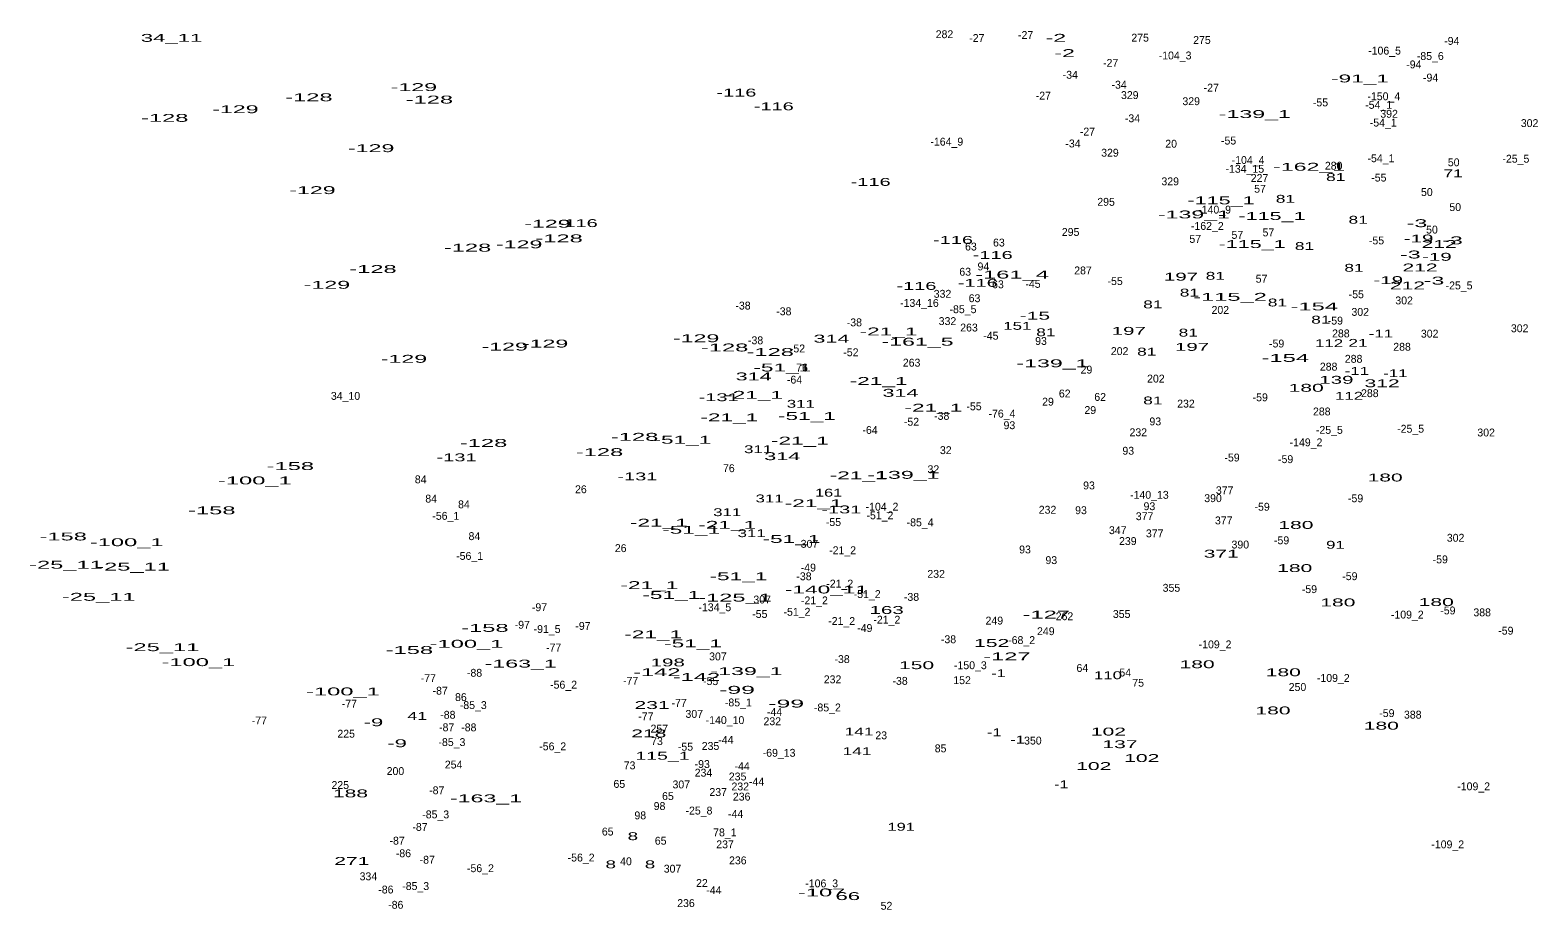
# Model space of a CAD drawing. Extents: x -662499 to -659675, y -1001682 to -998165.
# Drawn here: x -661764 to -660998, y -1000395 to -999948 of the extents above; entities that cross this region are included whole.
import ezdxf
from ezdxf.enums import TextEntityAlignment as Align

# ---------------------------------------------------------------- set-up
doc = ezdxf.new("R2010")
doc.units = 0
doc.header["$LTSCALE"] = 1.6
doc.layers.add('24', color=7, linetype='Continuous')

msp = doc.modelspace()

# ---------------------------------------------------------------- texts
at = {"layer": '24'}
for s, width, p in [('34_11', 2.1, (-661692.001, -999953.42)), ('-2', 2.2, (-661242.514, -999953.4)), ('-2', 2.2, (-661238.054, -999961.16)), ('-129', 2.2, (-661568.805, -999978.44)), ('-91_1', 2.15, (-661087.923, -999974.05)), ('-128', 2.25, (-661622.181, -999983.6)), ('-128', 2.25, (-661560.921, -999984.77)), ('-116', 1.9, (-661404.881, -999981.23)), ('-128', 2.25, (-661695.471, -999994.08)), ('-129', 2.2, (-661659.535, -999989.68)), ('-116', 1.9, (-661385.891, -999988.21)), ('-139_1', 2.2, (-661141.393, -999992.13)), ('-129', 2.2, (-661590.515, -1000009.47)), ('-162_1', 2.2, (-661113.763, -1000018.92)), ('81', 1.65, (-661100.267, -1000024.16)), ('71', 1.65, (-661040.593, -1000022.28)), ('-129', 2.2, (-661620.375, -1000030.8)), ('-116', 1.9, (-661336.641, -1000026.61)), ('-115_1', 2.05, (-661158.544, -1000035.99)), ('81', 1.65, (-661125.817, -1000035.2)), ('-129', 2.2, (-661500.945, -1000047.87)), ('-116', 1.9, (-661485.531, -1000047.56)), ('-139_1', 2.2, (-661172.333, -1000043.15)), ('-115_1', 2.05, (-661132.654, -1000043.94)), ('81', 1.65, (-661088.837, -1000045.85)), ('-3', 2.2, (-661058.934, -1000047.59)), ('-128', 2.25, (-661495.011, -1000055.31)), ('-116', 1.9, (-661294.771, -1000056.09)), ('-19', 1.95, (-661058.145, -1000055.38)), ('-3', 2.2, (-661040.904, -1000056.32)), ('-128', 2.25, (-661541.541, -1000060.02)), ('-129', 2.2, (-661515.295, -1000058.34)), ('-116', 1.9, (-661274.611, -1000063.76)), ('-115_1', 2.05, (-661142.734, -1000058.2)), ('81', 1.65, (-661116.137, -1000059.22)), ('-3', 2.2, (-661062.314, -1000063.5)), ('212', 2, (-661047.707, -1000058.19)), ('-128', 2.25, (-661589.611, -1000070.88)), ('81', 1.65, (-661090.967, -1000070.26)), ('212', 2, (-661057.407, -1000070.11)), ('-19', 1.95, (-661048.845, -1000064.68)), ('-129', 2.2, (-661613.005, -1000078.9)), ('-116', 1.9, (-661313.381, -1000079.47)), ('-116', 1.9, (-661282.171, -1000077.91)), ('-161_4', 2.25, (-661264.788, -1000073.7)), ('197', 1.95, (-661178.897, -1000074.77)), ('81', 1.65, (-661161.447, -1000074.33)), ('-19', 1.95, (-661073.555, -1000076.52)), ('212', 2, (-661063.797, -1000079.23)), ('-3', 2.2, (-661050.304, -1000076.78)), ('81', 1.65, (-661174.617, -1000082.85)), ('-115_2', 2.25, (-661153.987, -1000085.02)), ('-15', 2, (-661253.171, -1000094.61)), ('81', 1.65, (-661193.207, -1000088.86)), ('81', 1.65, (-661129.887, -1000087.89)), ('-154', 2.25, (-661111.156, -1000089.9)), ('-21_1', 2.15, (-661327.577, -1000102.61)), ('151', 1.6, (-661262.104, -1000099.76)), ('197', 1.95, (-661205.457, -1000102.31)), ('81', 1.65, (-661107.817, -1000096.61)), ('-129', 2.2, (-661522.665, -1000110.31)), ('-129', 2.2, (-661502.115, -1000108.76)), ('-129', 2.2, (-661425.345, -1000106.05)), ('314', 2.05, (-661356.573, -1000106.26)), ('-161_5', 2.2, (-661312.823, -1000107.81)), ('81', 1.65, (-661247.577, -1000103)), ('197', 1.95, (-661173.277, -1000110.45)), ('81', 1.65, (-661175.197, -1000103.19)), ('112', 1.6, (-661103.624, -1000108.56)), ('21', 1.65, (-661088.927, -1000108.41)), ('-11', 1.6, (-661077.297, -1000103.65)), ('-129', 2.2, (-661573.845, -1000116.52)), ('-128', 2.25, (-661410.871, -1000110.75)), ('-128', 2.25, (-661387.681, -1000113.07)), ('81', 1.65, (-661196.307, -1000112.88)), ('-154', 2.25, (-661125.896, -1000116.07)), ('314', 2.05, (-661396.123, -1000125.46)), ('-51_1', 2.15, (-661381.547, -1000120.95)), ('-139_1', 2.2, (-661244.253, -1000118.79)), ('-11', 1.6, (-661089.517, -1000122.66)), ('-11', 1.6, (-661069.937, -1000123.82)), ('-21_1', 2.15, (-661332.617, -1000127.79)), ('180', 2, (-661115.274, -1000131.24)), ('139', 1.95, (-661099.923, -1000127.18)), ('312', 2, (-661076.697, -1000128.94)), ('-131', 1.9, (-661413.917, -1000136.03)), ('-21_1', 2.15, (-661395.897, -1000134.82)), ('311', 1.6, (-661372.134, -1000139.37)), ('314', 2.05, (-661321.483, -1000133.8)), ('81', 1.65, (-661193.207, -1000137.67)), ('112', 1.6, (-661093.464, -1000135.29)), ('-21_1', 2.15, (-661408.497, -1000146.26)), ('-51_1', 2.15, (-661369.047, -1000145.58)), ('-21_1', 2.15, (-661304.757, -1000141.36)), ('-128', 2.25, (-661456.621, -1000156.16)), ('-128', 2.25, (-661533.391, -1000159.26)), ('-128', 2.25, (-661474.461, -1000163.92)), ('-51_1', 2.15, (-661432.347, -1000157.64)), ('311', 1.6, (-661393.844, -1000162.45)), ('-21_1', 2.15, (-661372.627, -1000158.09)), ('-158', 2.25, (-661631.601, -1000171.02)), ('-131', 1.9, (-661547.107, -1000166.58)), ('314', 2.05, (-661381.583, -1000165.99)), ('-100_1', 2.25, (-661649.65, -1000178.31)), ('-131', 1.9, (-661455.217, -1000176.27)), ('-21_1', 2.15, (-661342.777, -1000175.74)), ('-139_1', 2.2, (-661319.983, -1000175.47)), ('180', 2, (-661075.144, -1000176.82)), ('161', 1.55, (-661358.009, -1000184.54)), ('-158', 2.25, (-661671.531, -1000193.51)), ('311', 1.6, (-661409.544, -1000194.45)), ('311', 1.6, (-661388.024, -1000187.47)), ('-21_1', 2.15, (-661365.647, -1000189.89)), ('-131', 1.9, (-661351.547, -1000193.05)), ('-21_1', 2.15, (-661444.317, -1000199.79)), ('-21_1', 2.15, (-661409.577, -1000200.87)), ('180', 2, (-661120.504, -1000200.93)), ('-158', 2.25, (-661747.061, -1000206.79)), ('-100_1', 2.25, (-661714.79, -1000209.71)), ('-51_1', 2.15, (-661427.887, -1000203.39)), ('311', 1.6, (-661397.144, -1000205.12)), ('-51_1', 2.15, (-661376.897, -1000208.05)), ('371', 2, (-661158.443, -1000215.53)), ('91', 1.6, (-661100.403, -1000211.01)), ('-25_11', 2.25, (-661745.657, -1000221.16)), ('-25_11', 2.25, (-661711.537, -1000222.13)), ('180', 2, (-661121.084, -1000222.85)), ('-21_1', 2.15, (-661449.127, -1000231.51)), ('-51_1', 2.15, (-661403.847, -1000227)), ('-25_11', 2.25, (-661728.987, -1000237.45)), ('-51_1', 2.15, (-661437.967, -1000236.5)), ('-125_1', 2.25, (-661405.587, -1000237.86)), ('-140_11', 2.15, (-661359.126, -1000233.73)), ('180', 2, (-661099.184, -1000240.3)), ('180', 2, (-661049.164, -1000240.11)), ('163', 1.95, (-661328.513, -1000244.15)), ('-127', 2.25, (-661247.355, -1000246.49)), ('-158', 2.25, (-661532.721, -1000253.25)), ('-25_11', 2.25, (-661696.607, -1000263.05)), ('-100_1', 2.25, (-661542.06, -1000261.32)), ('-21_1', 2.15, (-661447.187, -1000256.53)), ('-51_1', 2.15, (-661426.917, -1000261.13)), ('152', 2, (-661275.127, -1000260.92)), ('-100_1', 2.25, (-661678.35, -1000270.65)), ('-158', 2.25, (-661571.111, -1000264.5)), ('-163_1', 2.2, (-661514.503, -1000271.4)), ('198', 1.95, (-661439.783, -1000270.8)), ('-127', 2.25, (-661267.415, -1000267.73)), ('-142', 2.25, (-661445.326, -1000275.75)), ('-142', 2.25, (-661425.166, -1000278.18)), ('-139_1', 2.2, (-661399.743, -1000275.21)), ('150', 2, (-661313.304, -1000272.2)), ('-1', 1.55, (-661271.691, -1000276.25)), ('110', 1.6, (-661216.02, -1000277.3)), ('180', 2, (-661170.714, -1000271.72)), ('180', 2, (-661126.904, -1000275.79)), ('-100_1', 2.25, (-661604.87, -1000285.54)), ('-99', 2.35, (-661404.573, -1000284.72)), ('231', 2, (-661447.757, -1000292.44)), ('-99', 2.35, (-661379.563, -1000291.7)), ('-9', 2.1, (-661589.379, -1000301.2)), ('41', 1.7, (-661567.083, -1000297.97)), ('180', 2, (-661132.134, -1000295.19)), ('218', 2, (-661449.397, -1000306.86)), ('141', 1.65, (-661342.519, -1000305.92)), ('-1', 1.55, (-661273.821, -1000306.32)), ('102', 2, (-661215.784, -1000305.93)), ('180', 2, (-661077.084, -1000302.94)), ('-9', 2.1, (-661577.359, -1000311.87)), ('141', 1.65, (-661343.579, -1000315.91)), ('-1', 1.55, (-661262.001, -1000310)), ('137', 2, (-661209.913, -1000312.35)), ('115_1', 1.85, (-661442.461, -1000318.22)), ('102', 2, (-661223.234, -1000323.46)), ('102', 2, (-661198.834, -1000319.39)), ('-1', 1.55, (-661239.701, -1000332.69)), ('188', 2, (-661601.037, -1000337.35)), ('-163_1', 2.2, (-661532.143, -1000339.86)), ('191', 1.55, (-661321.129, -1000354.3)), ('8', 1.8, (-661457.511, -1000359.08)), ('271', 2, (-661600.343, -1000371.67)), ('8', 1.8, (-661468.741, -1000373.41)), ('8', 1.8, (-661448.791, -1000373.41)), ('-107', 2.25, (-661361.551, -1000387.68)), ('66', 2.1, (-661348.251, -1000389.55))]:
    msp.add_text(s, height=4, dxfattribs=dict(at, width=width)).set_placement(p, align=Align.CENTER)
for s, p in [('282', (-661299.117, -999951.56)), ('-27', (-661282.681, -999953.52)), ('-27', (-661257.871, -999951.97)), ('275', (-661199.663, -999953.32)), ('275', (-661168.263, -999954.49)), ('-94', (-661041.265, -999954.98)), ('-104_3', (-661181.904, -999962.36)), ('-106_5', (-661075.436, -999959.91)), ('-85_6', (-661052.188, -999962.65)), ('-34', (-661235.169, -999972.18)), ('-27', (-661214.641, -999966.13)), ('-94', (-661060.555, -999966.9)), ('-34', (-661210.349, -999977.22)), ('-27', (-661163.511, -999978.73)), ('-94', (-661052.025, -999973.59)), ('-27', (-661248.851, -999982.76)), ('329', (-661204.933, -999982.5)), ('329', (-661173.713, -999985.6)), ('-55', (-661107.985, -999986.22)), ('-54_1', (-661078.42, -999987.45)), ('-150_4', (-661075.804, -999983.11)), ('-34', (-661203.569, -999994.29)), ('392', (-661073.123, -999992)), ('-27', (-661226.461, -1000001.04)), ('-54_1', (-661076.1, -999996.46)), ('302', (-661001.711, -999996.74)), ('-164_9', (-661297.941, -1000006.16)), ('-34', (-661233.809, -1000007.09)), ('20', (-661183.911, -1000007.21)), ('-55', (-661154.705, -1000005.61)), ('329', (-661215.013, -1000011.78)), ('-104_4', (-661144.809, -1000015.51)), ('280', (-661101.311, -1000018.39)), ('-54_1', (-661077.26, -1000014.6)), ('50', (-661040.291, -1000016.66)), ('-25_5', (-661008.682, -1000014.83)), ('329', (-661184.383, -1000026.33)), ('-134_15', (-661146.463, -1000019.95)), ('227', (-661138.983, -1000024.61)), ('-55', (-661078.325, -1000024.42)), ('57', (-661138.733, -1000030.1)), ('50', (-661053.941, -1000031.77)), ('295', (-661216.973, -1000036.74)), ('-140_9', (-661161.83, -1000040.71)), ('50', (-661039.521, -1000039.42)), ('-162_2', (-661165.522, -1000048.99)), ('295', (-661235.003, -1000052.06)), ('57', (-661171.653, -1000055.58)), ('57', (-661150.253, -1000053.54)), ('57', (-661134.473, -1000052.28)), ('-55', (-661079.525, -1000056.36)), ('50', (-661051.331, -1000050.85)), ('63', (-661285.683, -1000059.47)), ('63', (-661271.453, -1000057.44)), ('63', (-661288.593, -1000072.26)), ('94', (-661279.337, -1000069.56)), ('287', (-661228.713, -1000071.6)), ('63', (-661271.943, -1000078.66)), ('-45', (-661254.119, -1000078.42)), ('-55', (-661212.365, -1000077.02)), ('57', (-661137.953, -1000075.82)), ('-25_5', (-661037.562, -1000079.22)), ('332', (-661300.117, -1000083.48)), ('63', (-661283.843, -1000085.72)), ('-55', (-661089.795, -1000083.71)), ('302', (-661065.491, -1000086.84)), ('-38', (-661401.525, -1000089.47)), ('-38', (-661380.775, -1000092.37)), ('-134_16', (-661311.859, -1000088.1)), ('-85_5', (-661289.722, -1000091.31)), ('202', (-661158.911, -1000091.66)), ('302', (-661087.791, -1000092.66)), ('-38', (-661344.915, -1000098)), ('332', (-661297.597, -1000097.35)), ('263', (-661286.643, -1000100.62)), ('-59', (-661100.43, -1000097.1)), ('302', (-661006.751, -1000101)), ('-38', (-661395.125, -1000107.11)), ('-45', (-661275.539, -1000104.79)), ('93', (-661250.053, -1000107.44)), ('-59', (-661130.29, -1000108.74)), ('288', (-661097.647, -1000103.61)), ('288', (-661066.537, -1000110.4)), ('302', (-661052.501, -1000103.72)), ('-52', (-661373.835, -1000111.25)), ('-52', (-661346.685, -1000113.19)), ('202', (-661210.091, -1000112.6)), ('288', (-661091.157, -1000116.51)), ('76', (-661371.548, -1000120.96)), ('263', (-661315.823, -1000118.47)), ('29', (-661226.953, -1000122.02)), ('288', (-661103.857, -1000120.49)), ('-64', (-661375.345, -1000127.09)), ('202', (-661191.671, -1000126.57)), ('34_10', (-661603.547, -1000135.35)), ('-55', (-661284.095, -1000140.64)), ('29', (-661246.513, -1000138.29)), ('62', (-661237.993, -1000134.14)), ('62', (-661219.983, -1000135.88)), ('232', (-661176.377, -1000139.29)), ('-59', (-661138.62, -1000136.08)), ('288', (-661082.917, -1000133.97)), ('-52', (-661315.875, -1000148.49)), ('-38', (-661300.515, -1000145.51)), ('-76_4', (-661269.898, -1000144.36)), ('29', (-661225.023, -1000142.56)), ('93', (-661191.963, -1000148.31)), ('288', (-661107.347, -1000143.27)), ('-64', (-661336.955, -1000152.69)), ('93', (-661266.123, -1000150.25)), ('232', (-661200.607, -1000153.84)), ('-25_5', (-661103.482, -1000152.63)), ('-25_5', (-661062.192, -1000152.05)), ('302', (-661023.811, -1000153.95)), ('32', (-661298.457, -1000162.93)), ('93', (-661205.713, -1000163.23)), ('-149_2', (-661115.356, -1000158.96)), ('-59', (-661152.97, -1000166.67)), ('-59', (-661125.73, -1000167.5)), ('84', (-661565.361, -1000177.77)), ('76', (-661408.728, -1000172.1)), ('32', (-661304.747, -1000172.62)), ('26', (-661483.933, -1000182.8)), ('93', (-661225.653, -1000180.85)), ('-140_13', (-661194.957, -1000185.63)), ('377', (-661156.709, -1000183.31)), ('84', (-661560.031, -1000187.55)), ('84', (-661543.381, -1000190.46)), ('-104_2', (-661330.874, -1000191.65)), ('232', (-661246.747, -1000193.21)), ('93', (-661229.723, -1000193.44)), ('93', (-661194.953, -1000191.42)), ('390', (-661162.617, -1000187.33)), ('-59', (-661137.65, -1000191.69)), ('-59', (-661090.16, -1000187.4)), ('-56_1', (-661552.602, -1000196.31)), ('-55', (-661355.555, -1000199.46)), ('-51_2', (-661331.926, -1000196.04)), ('-85_4', (-661311.507, -1000199.62)), ('377', (-661197.419, -1000196.49)), ('377', (-661157.189, -1000198.63)), ('84', (-661538.061, -1000206.63)), ('347', (-661211.047, -1000203.59)), ('239', (-661205.933, -1000209.12)), ('377', (-661192.279, -1000205.21)), ('-59', (-661127.77, -1000208.74)), ('302', (-661039.321, -1000207.45)), ('-56_1', (-661540.482, -1000216.67)), ('26', (-661463.693, -1000212.72)), ('307', (-661367.747, -1000210.52)), ('-21_2', (-661350.906, -1000213.78)), ('93', (-661258.183, -1000213.39)), ('390', (-661148.757, -1000210.89)), ('-49', (-661368.315, -1000222.58)), ('93', (-661244.823, -1000218.82)), ('-59', (-661047.12, -1000218.43)), ('-38', (-661370.545, -1000227.02)), ('-21_2', (-661352.356, -1000230.75)), ('232', (-661303.357, -1000225.79)), ('355', (-661183.757, -1000232.88)), ('-59', (-661093.06, -1000226.97)), ('307', (-661391.797, -1000238.83)), ('-21_2', (-661365.246, -1000239.28)), ('-51_2', (-661338.416, -1000236.07)), ('-38', (-661315.875, -1000237.49)), ('-59', (-661113.61, -1000233.56)), ('-97', (-661504.975, -1000242.74)), ('-134_5', (-661415.85, -1000242.76)), ('-55', (-661392.975, -1000246.17)), ('-51_2', (-661374.096, -1000245.08)), ('262', (-661238.133, -1000247.33)), ('355', (-661209.057, -1000246.17)), ('-109_2', (-661063.876, -1000246.49)), ('-59', (-661043.24, -1000244.38)), ('388', (-661025.817, -1000245.35)), ('-97', (-661513.705, -1000251.66)), ('-91_5', (-661501.102, -1000253.82)), ('-97', (-661482.875, -1000252.24)), ('-21_2', (-661351.386, -1000249.76)), ('-49', (-661339.625, -1000253.32)), ('-21_2', (-661328.416, -1000249.08)), ('249', (-661273.787, -1000249.54)), ('249', (-661247.617, -1000254.92)), ('-59', (-661013.77, -1000254.66)), ('-77', (-661497.775, -1000263.24)), ('-38', (-661297.065, -1000259.02)), ('-68_2', (-661259.908, -1000259.45)), ('-109_2', (-661161.586, -1000261.62)), ('307', (-661414.277, -1000267.73)), ('-38', (-661351.155, -1000269.11)), ('-77', (-661561.465, -1000278.76)), ('-88', (-661537.975, -1000276.07)), ('-150_3', (-661285.96, -1000272.22)), ('64', (-661229.047, -1000273.62)), ('54', (-661207.231, -1000275.91)), ('-109_2', (-661101.486, -1000278.68)), ('-87', (-661555.441, -1000285.16)), ('-56_2', (-661492.728, -1000282.1)), ('-77', (-661458.615, -1000280.12)), ('-55', (-661417.975, -1000280.3)), ('232', (-661356.007, -1000279.39)), ('-38', (-661321.685, -1000280.16)), ('152', (-661290.169, -1000279.82)), ('75', (-661200.683, -1000281.14)), ('250', (-661119.691, -1000283.29)), ('-77', (-661601.595, -1000291.75)), ('86', (-661544.913, -1000288.43)), ('-85_3', (-661538.632, -1000292.48)), ('-77', (-661433.995, -1000291.36)), ('-85_1', (-661403.896, -1000291.13)), ('-85_2', (-661358.642, -1000293.68)), ('-77', (-661647.345, -1000300.29)), ('-88', (-661551.545, -1000297.4)), ('-77', (-661450.865, -1000298.15)), ('307', (-661426.297, -1000296.95)), ('-140_10', (-661410.681, -1000300.11)), ('232', (-661386.647, -1000300.68)), ('-44', (-661385.503, -1000295.97)), ('-59', (-661074.26, -1000296.55)), ('388', (-661061.097, -1000297.33)), ('225', (-661603.237, -1000307.02)), ('-87', (-661552.141, -1000303.77)), ('-88', (-661540.885, -1000303.8)), ('257', (-661444.063, -1000304.42)), ('23', (-661331.277, -1000307.84)), ('-85_3', (-661549.482, -1000311.29)), ('-56_2', (-661498.248, -1000313.44)), ('73', (-661445.243, -1000310.78)), ('-55', (-661430.775, -1000313.63)), ('235', (-661418.037, -1000313.25)), ('-44', (-661410.223, -1000310.13)), ('-69_13', (-661383.187, -1000316.72)), ('85', (-661301.097, -1000314.46)), ('350', (-661254.191, -1000310.51)), ('254', (-661548.621, -1000322.69)), ('73', (-661459.173, -1000323.09)), ('-93', (-661422.24, -1000322.43)), ('-44', (-661401.983, -1000323.49)), ('200', (-661578.185, -1000326)), ('65', (-661464.383, -1000332.53)), ('307', (-661432.897, -1000332.79)), ('234', (-661421.621, -1000326.82)), ('235', (-661404.267, -1000328.76)), ('-44', (-661394.613, -1000331.37)), ('225', (-661606.247, -1000333.1)), ('-87', (-661557.181, -1000335.77)), ('65', (-661439.693, -1000338.73)), ('237', (-661414.143, -1000336.66)), ('232', (-661402.927, -1000333.83)), ('236', (-661402.213, -1000338.99)), ('-109_2', (-661030.136, -1000333.76)), ('-85_3', (-661557.722, -1000348.02)), ('98', (-661443.953, -1000343.77)), ('-25_8', (-661423.912, -1000346.07)), ('-44', (-661405.273, -1000347.8)), ('-87', (-661565.711, -1000354.39)), ('98', (-661453.733, -1000348.51)), ('-87', (-661577.341, -1000361.37)), ('65', (-661470.293, -1000356.74)), ('65', (-661443.373, -1000361.39)), ('78_1', (-661410.754, -1000357.16)), ('237', (-661410.653, -1000363.23)), ('-109_2', (-661043.326, -1000363.24)), ('-86', (-661574.13, -1000367.77)), ('-87', (-661562.031, -1000371.07)), ('-56_2', (-661483.808, -1000369.95)), ('-56_2', (-661534.988, -1000375.36)), ('40', (-661461.005, -1000371.86)), ('307', (-661437.347, -1000375.6)), ('236', (-661404.153, -1000371.38)), ('334', (-661591.941, -1000379.49)), ('-86', (-661583.05, -1000386.2)), ('-85_3', (-661567.902, -1000384.43)), ('22', (-661422.407, -1000382.88)), ('-106_3', (-661361.536, -1000383.07)), ('-86', (-661578.01, -1000393.96)), ('236', (-661430.513, -1000393.1)), ('-44', (-661416.333, -1000386.5)), ('52', (-661328.597, -1000394.46))]:
    msp.add_text(s, height=4, dxfattribs=at).set_placement(p, align=Align.CENTER)

doc.saveas('drawing.dxf')
